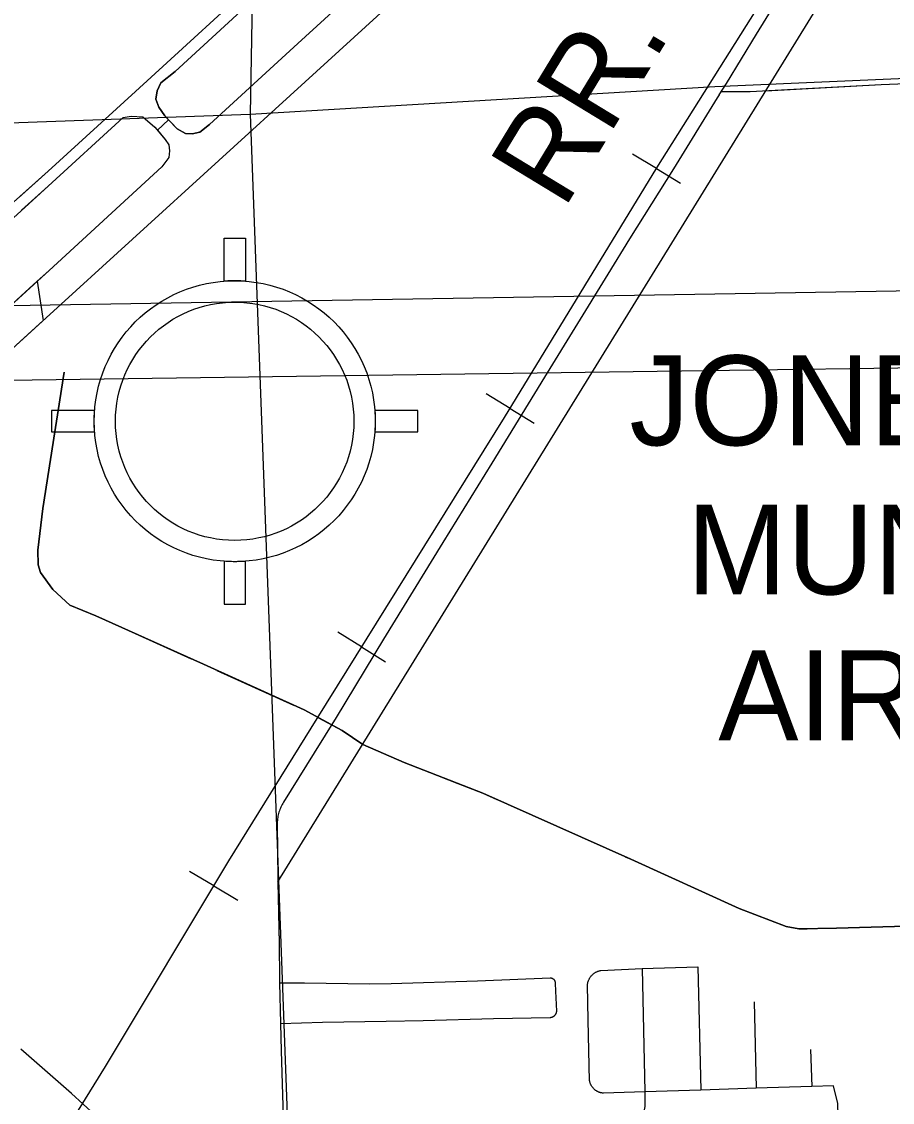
# Model space of a CAD drawing. Extents: x 646058 to 725608, y 1473014 to 1561048.
# Drawn here: x 652089 to 654134, y 1553140 to 1555679 of the extents above; entities that cross this region are included whole.
import ezdxf

# ---------------------------------------------------------------- set-up
doc = ezdxf.new("R2010")
doc.units = 0
doc.layers.add('Default', color=7, linetype='Continuous')

msp = doc.modelspace()

# ---------------------------------------------------------------- linework, layer by layer
at = {"layer": 'Default'}
for p, q in [((653579.7, 1555333.9), (653523.3, 1555368.3)), ((653579.7, 1555333.9), (653636, 1555299.6)), ((652564.4, 1555069.4), (652564.4, 1555170.4)), ((652564.4, 1555170.4), (652614.4, 1555170.4)), ((653236.1, 1554770.4), (653179.7, 1554804.8)), ((652260.3, 1554765.4), (652159.4, 1554765.4)), ((652159.4, 1554765.4), (652159.4, 1554715.4)), ((653019.4, 1554765.4), (652918.4, 1554765.4)), ((653019.4, 1554715.4), (653019.4, 1554765.4)), ((653236.1, 1554770.4), (653292.4, 1554736)), ((652614.4, 1554310.4), (652614.4, 1554411.3)), ((652564.4, 1554310.4), (652614.4, 1554310.4)), ((652887.3, 1554210.1), (652831.3, 1554245)), ((652887.3, 1554210.1), (652943.3, 1554175.2)), ((652540.1, 1553648.8), (652483.5, 1553682.7)), ((652540.1, 1553648.8), (652596.7, 1553614.9))]:
    msp.add_line(p, q, dxfattribs=at)
for points in [[(652603.7, 1558110.8), (652645.2, 1556568.6), (652625.6, 1555461.7)], [(652690.8, 1553657.9), (654107.8, 1555957.2), (654213.4, 1556124.9), (654316.1, 1556289.2), (654433.5, 1556478.3), (654545.6, 1556660.4), (654677, 1556873.8), (654783, 1557046.2), (654897.1, 1557233.3), (655061.6, 1557505.5), (655230.6, 1557774.9)], [(652151.1, 1555327.8), (652356.1, 1555515), (652677.9, 1555810.5), (653077.1, 1556176.4)], [(653077.1, 1556176.4), (652677.9, 1555810.5), (652356.1, 1555515), (652151.1, 1555327.8)], [(653097.4, 1556153.5), (652777.3, 1555864.2), (652449.3, 1555562.5), (652415.9, 1555535.2), (652407.1, 1555516.8), (652404.5, 1555497.4), (652411.5, 1555478.1), (652425.6, 1555457.8), (652454.6, 1555427.1), (652474, 1555416.5), (652489.8, 1555415.6), (652507.4, 1555420), (652530.2, 1555437.6), (652737.7, 1555627.6), (653219.6, 1556069.1)], [(652434.3, 1555448.6), (652425.6, 1555457.8), (652411.5, 1555478.1), (652404.5, 1555497.4), (652407.1, 1555516.8), (652415.9, 1555535.2), (652449.3, 1555562.5), (652777.3, 1555864.2), (653097.4, 1556153.5)], [(653219.6, 1556069.1), (652737.7, 1555627.6), (652530.2, 1555437.6), (652507.4, 1555420), (652489.8, 1555415.6), (652474, 1555416.5), (652454.6, 1555427.1), (652434.3, 1555448.6)], [(652146.4, 1554983.1), (652755.3, 1555537.5), (653286.4, 1556023.3)], [(652146.4, 1554983.1), (652755.3, 1555537.5), (653286.4, 1556023.3)], [(653727.1, 1555507.2), (653744.3, 1555534.3), (653815.2, 1555649.7), (653909.8, 1555804.3)], [(650469, 1550273.7), (650551.1, 1550406.6), (650698, 1550644.3), (650864.5, 1550916.9), (651062.8, 1551236.4), (651236.9, 1551521.1), (651402, 1551789.1), (651583.7, 1552081.4), (651698.7, 1552273.7), (651957.6, 1552696.2), (652122.6, 1552959.6), (652286.2, 1553224.6), (652575.3, 1553707.7), (652782.8, 1554042.3), (653223.3, 1554749.5), (653580.6, 1555335.5), (653813.8, 1555706.5)], [(650469, 1550273.7), (650551.1, 1550406.6), (650698, 1550644.3), (650864.5, 1550916.9), (651062.8, 1551236.4), (651236.9, 1551521.1), (651402, 1551789.1), (651583.7, 1552081.4), (651698.7, 1552273.7), (651957.6, 1552696.2), (652122.6, 1552959.6), (652286.2, 1553224.6), (652575.3, 1553707.7), (652782.8, 1554042.3), (653223.3, 1554749.5), (653580.6, 1555335.5), (653813.8, 1555706.5)], [(651957.6, 1552696.2), (652122.6, 1552959.6), (652286.2, 1553224.6), (652575.3, 1553707.7), (652782.8, 1554042.3), (653223.3, 1554749.5), (653580.6, 1555335.5), (653813.8, 1555706.5)], [(653732.3, 1555515.5), (653800.2, 1555515), (654107.4, 1555532), (654344.2, 1555541.3), (654528.4, 1555548.2), (654865, 1555563.7), (655077, 1555572.2), (655262.7, 1555580.8), (655436.8, 1555586.2), (655707.7, 1555594.7), (655830.7, 1555596.2), (655923.6, 1555600.1), (656045, 1555604), (656446.7, 1555620.2), (656625.4, 1555628), (656926.4, 1555639.6), (657231.3, 1555648.1), (657507.6, 1555658.2), (657676.3, 1555663.6), (657882.9, 1555670.5)], [(653836.5, 1555517), (654107.4, 1555532), (654344.2, 1555541.3), (654528.4, 1555548.2), (654865, 1555563.7), (655077, 1555572.2), (655262.7, 1555580.8), (655436.8, 1555586.2), (655707.7, 1555594.7), (655830.7, 1555596.2), (655923.6, 1555600.1), (656045, 1555604), (656446.7, 1555620.2), (656625.4, 1555628), (656926.4, 1555639.6), (657231.3, 1555648.1), (657507.6, 1555658.2), (657676.3, 1555663.6), (657882.9, 1555670.5)], [(652625.6, 1555461.7), (653716.8, 1555527), (655261.9, 1555594.5)], [(653727.1, 1555507.2), (653722.4, 1555499.9), (653619.7, 1555333.7), (653516.5, 1555169), (653465.4, 1555086.3), (653317.3, 1554844.1), (653193.1, 1554642.2), (653078.2, 1554455.3), (652938.8, 1554228.2), (652827.6, 1554044.2), (652775.8, 1553961.6), (652703.9, 1553845.4), (652702.3, 1553842.6), (652700.7, 1553839.8), (652699.3, 1553836.9), (652697.9, 1553834), (652696.6, 1553831), (652695.4, 1553828), (652694.4, 1553824.9), (652693.4, 1553821.8)], [(649972.5, 1555366.3), (652625.6, 1555461.7)], [(652151.1, 1555292.9), (652327.1, 1555453.9), (652346.5, 1555457.4), (652373.7, 1555455.7), (652401.9, 1555431), (652426.5, 1555402), (652434.4, 1555389.7), (652436.1, 1555375.6), (652434.4, 1555359.8), (652418.6, 1555337.8), (652153.4, 1555094.6)], [(652151.1, 1555292.9), (652327.1, 1555453.9), (652346.5, 1555457.4), (652373.7, 1555455.7), (652401.9, 1555431), (652407.9, 1555424)], [(652407.9, 1555424), (652434.3, 1555448.6)], [(652625.6, 1555461.7), (652721.9, 1552858.1)], [(652407.9, 1555424), (652426.5, 1555402), (652434.4, 1555389.7), (652436.1, 1555375.6), (652434.4, 1555359.8), (652418.6, 1555337.8), (652153.4, 1555094.6)], [(651734.2, 1555260.9), (651788.2, 1555306.1), (651799.1, 1555317), (651801.4, 1555332.5), (651800.6, 1555356.6), (651834, 1555357.4), (651837.9, 1555174.7), (651862.8, 1555161.5), (651864.3, 1555119.5), (651872.1, 1555105.5), (651879.9, 1555101.6), (651896.2, 1555102.4), (651906.3, 1555109.4), (652151.1, 1555327.8)], [(652151.1, 1555327.8), (652081.4, 1555265.6)], [(652151.1, 1555292.9), (651870.6, 1555036.4), (651874.4, 1554940), (651884.5, 1554920.5), (651900.9, 1554905.8), (651914.9, 1554901.1), (651934.3, 1554901.9), (651947.5, 1554908.1), (651963.8, 1554921.3), (652153.4, 1555094.6)], [(652089, 1555236.1), (652151.1, 1555292.9)], [(668379.5, 1555281.6), (649175.8, 1554963.8)], [(668379.5, 1555281.6), (649175.8, 1554963.8)], [(652614.4, 1555170.4), (652614.4, 1555069.4), (652611, 1555069.7), (652607.6, 1555069.9), (652604.2, 1555070.1), (652600, 1555070.2), (652596.3, 1555070.3), (652591.7, 1555070.4), (652588.8, 1555070.4), (652584.7, 1555070.4), (652580.8, 1555070.3), (652577.3, 1555070.2), (652573.3, 1555070), (652570.1, 1555069.8), (652567.2, 1555069.6), (652564.4, 1555069.4)], [(652153.4, 1555094.6), (652125.9, 1555069.5)], [(649175.8, 1554797.2), (668379.5, 1555063.1)], [(649175.8, 1554797.2), (668379.5, 1555063.1)], [(651874.4, 1554940), (651884.5, 1554920.5), (651900.9, 1554905.8), (651914.9, 1554901.1), (651934.3, 1554901.9), (651947.5, 1554908.1), (651963.8, 1554921.3), (652125.9, 1555069.5)], [(652125.9, 1555069.5), (652139.9, 1554977.2)], [(652125.9, 1555069.5), (652139.9, 1554977.2)], [(652146.4, 1554983.1), (651887.7, 1554747.6), (651885.3, 1554743.7), (651886.1, 1554708.8), (651895.4, 1554561.1), (651873.7, 1554539.3), (651872.9, 1554527.7), (651896.2, 1554061.3), (651909.1, 1553842.5)], [(652139.9, 1554977.2), (651887.7, 1554747.6), (651885.3, 1554743.7), (651886.1, 1554708.8), (651895.4, 1554561.1), (651873.7, 1554539.3), (651872.9, 1554527.7), (651895.7, 1554072)], [(654002.5, 1553549.5), (653914.5, 1553547.7), (653884.2, 1553553.2), (653774.2, 1553595.8), (653519.8, 1553711.3), (653171.9, 1553866.8), (652987.7, 1553938.3), (652890, 1553980.9), (652841.9, 1554013.9), (652752.5, 1554062.1), (652516, 1554169.4), (652263, 1554283.5), (652202.5, 1554308.3), (652162.6, 1554345.4), (652133.7, 1554385.3), (652128.2, 1554403.2), (652126.8, 1554437.6), (652139.2, 1554535.2), (652188.7, 1554855.7)], [(652188.7, 1554855.7), (652139.2, 1554535.2), (652126.8, 1554437.6), (652128.2, 1554403.2), (652133.7, 1554385.3), (652162.6, 1554345.4), (652202.5, 1554308.3), (652263, 1554283.5), (652516, 1554169.4), (652752.5, 1554062.1), (652841.9, 1554013.9), (652890, 1553980.9), (652987.7, 1553938.3), (653171.9, 1553866.8), (653519.8, 1553711.3), (653774.2, 1553595.8), (653884.2, 1553553.2), (653914.5, 1553547.7), (654002.5, 1553549.5)], [(652159.4, 1554715.4), (652260.3, 1554715.4), (652260.1, 1554718.2), (652259.9, 1554721.6), (652259.8, 1554724.4), (652259.7, 1554726.7), (652259.5, 1554729.8), (652259.5, 1554732.6), (652259.4, 1554736.8), (652259.4, 1554740.4), (652259.4, 1554744.3), (652259.5, 1554747.7), (652259.6, 1554751.1), (652259.6, 1554753.8), (652259.8, 1554756.9), (652259.9, 1554759.4), (652260.1, 1554761.5), (652260.2, 1554763.4), (652260.3, 1554765.4)], [(652918.4, 1554765.4), (652918.5, 1554764.2), (652918.6, 1554762.6), (652918.7, 1554761.3), (652918.8, 1554759.9), (652918.9, 1554758.2), (652919, 1554756.8), (652919, 1554755.1), (652919.1, 1554753.8), (652919.2, 1554751.9), (652919.2, 1554750.5), (652919.3, 1554749), (652919.3, 1554747.1), (652919.3, 1554745.5), (652919.4, 1554744), (652919.4, 1554742.2), (652919.4, 1554740.5), (652919.4, 1554738.6), (652919.4, 1554736.5), (652919.3, 1554734.6), (652919.3, 1554731.9), (652919.2, 1554729.3), (652919.1, 1554727.7), (652919, 1554725.5), (652918.9, 1554723.2), (652918.8, 1554720.3), (652918.6, 1554718.1), (652918.4, 1554715.4), (653019.4, 1554715.4)], [(652614.4, 1554411.3), (652612.7, 1554411.2), (652610.6, 1554411.1), (652607.9, 1554410.9), (652604.7, 1554410.8), (652601.9, 1554410.6), (652599.1, 1554410.5), (652596.1, 1554410.5), (652593.7, 1554410.4), (652590, 1554410.4), (652585.6, 1554410.4), (652582, 1554410.5), (652578.3, 1554410.6), (652575.3, 1554410.7), (652571.1, 1554410.9), (652568.4, 1554411.1), (652564.4, 1554411.3), (652564.4, 1554310.4)], [(652306.8, 1554263.7), (652487.3, 1554182.3)], [(652547.4, 1554155.1), (652727.7, 1554073.3)], [(652786.6, 1554043.7), (652841.9, 1554013.9), (652890, 1553980.9), (652960.5, 1553950.1)], [(653021.5, 1553925.1), (653113.8, 1553889.3)], [(653113.8, 1553889.3), (653171.9, 1553866.8), (653205.4, 1553851.8)], [(652693.4, 1553821.8), (652692.5, 1553818.7), (652691.8, 1553815.6), (652691.1, 1553812.4), (652690.5, 1553809.2), (652690.1, 1553806), (652689.7, 1553802.8), (652689.5, 1553799.5), (652689.4, 1553796.3), (652690.7, 1553664.2), (652693.9, 1553512.8), (652694.3, 1553431), (652694.6, 1553421.2)], [(653265.7, 1553824.9), (653446.5, 1553744.1)], [(653506.7, 1553717.2), (653519.8, 1553711.3), (653687, 1553635.4)], [(652690.8, 1553657.9), (652693.9, 1553512.8), (652694.3, 1553431), (652694.6, 1553421.2)], [(653747.1, 1553608.1), (653774.2, 1553595.8), (653884.2, 1553553.2), (653914.5, 1553547.7), (653934, 1553548.1)], [(656022.1, 1551653.3), (656016.5, 1551688.2), (656011.1, 1551986.3), (655995, 1552500.7), (655983, 1552926.4), (655973.6, 1553146.6), (655964.2, 1553556.2), (655958.8, 1553599.2), (655921.2, 1553607.3), (655746.6, 1553601.9), (655505, 1553596.5), (655347.9, 1553593.9), (655247.2, 1553587.1), (654926.3, 1553576.4), (654515.4, 1553565.6), (654193.2, 1553554.9), (654002.5, 1553549.5)], [(654002.5, 1553549.5), (654193.2, 1553554.9), (654515.4, 1553565.6), (654926.3, 1553576.4), (655247.2, 1553587.1), (655347.9, 1553593.9), (655505, 1553596.5), (655746.6, 1553601.9), (655921.2, 1553607.3), (655958.8, 1553599.2), (655964.2, 1553556.2), (655973.6, 1553146.6), (655976.4, 1553079.7)], [(654000, 1553549.5), (654002.5, 1553549.5)], [(654002.5, 1553549.5), (654101.5, 1553552.3)], [(653419.5, 1553333.2), (653417.7, 1553416.1), (653417.9, 1553417.5), (653418.2, 1553418.9), (653418.4, 1553420.2), (653418.7, 1553421.5), (653419.1, 1553422.9), (653419.5, 1553424.2), (653420, 1553425.5), (653420.5, 1553426.7), (653421, 1553428), (653421.6, 1553429.2), (653422.3, 1553430.4), (653422.9, 1553431.6), (653423.7, 1553432.8), (653424.4, 1553433.9), (653425.2, 1553435.1), (653426, 1553436.1), (653426.9, 1553437.2), (653427.8, 1553438.2)], [(653419.5, 1553333.2), (653417.7, 1553416.1), (653417.9, 1553417.5), (653418.2, 1553418.9), (653418.4, 1553420.2), (653418.7, 1553421.5), (653419.1, 1553422.9), (653419.5, 1553424.2), (653420, 1553425.5), (653420.5, 1553426.7), (653421, 1553428), (653421.6, 1553429.2), (653422.3, 1553430.4), (653422.9, 1553431.6), (653423.7, 1553432.8), (653424.4, 1553433.9), (653425.2, 1553435.1), (653426, 1553436.1), (653426.9, 1553437.2), (653427.8, 1553438.2)], [(653427.8, 1553438.2), (653428.8, 1553439.2), (653429.7, 1553440.2), (653430.8, 1553441.1), (653431.8, 1553442), (653432.9, 1553442.9), (653434, 1553443.7), (653435.1, 1553444.4), (653436.3, 1553445.2), (653437.4, 1553445.9), (653438.6, 1553446.5), (653439.9, 1553447.1), (653441.1, 1553447.7), (653442.4, 1553448.2), (653443.7, 1553448.7), (653445, 1553449.1), (653446.3, 1553449.5), (653447.6, 1553449.9), (653448.9, 1553450.2), (653546.3, 1553454.3)], [(653427.8, 1553438.2), (653428.8, 1553439.2), (653429.7, 1553440.2), (653430.8, 1553441.1), (653431.8, 1553442), (653432.9, 1553442.9), (653434, 1553443.7), (653435.1, 1553444.4), (653436.3, 1553445.2), (653437.4, 1553445.9), (653438.6, 1553446.5), (653439.9, 1553447.1), (653441.1, 1553447.7), (653442.4, 1553448.2), (653443.7, 1553448.7), (653445, 1553449.1), (653446.3, 1553449.5), (653447.6, 1553449.9), (653448.9, 1553450.2), (653546.3, 1553454.3)], [(653546.3, 1553454.3), (653676.8, 1553458.2)], [(653546.3, 1553454.3), (653676.8, 1553458.2)], [(653546.3, 1553454.3), (653552.8, 1553164.7)], [(653546.3, 1553454.3), (653552.8, 1553164.7)], [(653676.8, 1553458.2), (653684.2, 1553168.9)], [(653676.8, 1553458.2), (653684.2, 1553168.9)], [(652694.6, 1553421.2), (652753.4, 1553421.1), (652855.4, 1553419.4), (652906.1, 1553418.5), (652956.8, 1553419.3), (653160, 1553426), (653330.6, 1553432.8), (653331, 1553432.7), (653331.5, 1553432.7), (653331.9, 1553432.6), (653332.4, 1553432.5), (653332.8, 1553432.4), (653333.3, 1553432.3), (653333.7, 1553432.1), (653334.2, 1553432), (653334.6, 1553431.8), (653335, 1553431.6), (653335.4, 1553431.4), (653335.9, 1553431.2), (653336.3, 1553431), (653336.6, 1553430.7), (653337, 1553430.5), (653337.4, 1553430.2), (653337.8, 1553429.9), (653338.1, 1553429.7), (653338.5, 1553429.3), (653338.8, 1553429), (653339.2, 1553428.7)], [(652694.6, 1553421.2), (652753.4, 1553421.1), (652855.4, 1553419.4), (652906.1, 1553418.5), (652956.8, 1553419.3), (653160, 1553426), (653330.6, 1553432.8), (653331, 1553432.7), (653331.5, 1553432.7), (653331.9, 1553432.6), (653332.4, 1553432.5), (653332.8, 1553432.4), (653333.3, 1553432.3), (653333.7, 1553432.1), (653334.2, 1553432), (653334.6, 1553431.8), (653335, 1553431.6), (653335.4, 1553431.4), (653335.9, 1553431.2), (653336.3, 1553431), (653336.6, 1553430.7), (653337, 1553430.5), (653337.4, 1553430.2), (653337.8, 1553429.9), (653338.1, 1553429.7), (653338.5, 1553429.3), (653338.8, 1553429), (653339.2, 1553428.7)], [(652694.6, 1553421.2), (652697.1, 1553325.1)], [(652694.6, 1553421.2), (652697.1, 1553325.1)], [(653340.9, 1553344.1), (653341.3, 1553344.5), (653341.6, 1553344.9), (653342, 1553345.3), (653342.3, 1553345.7), (653342.6, 1553346.2), (653343, 1553346.6), (653343.3, 1553347), (653343.5, 1553347.5), (653343.8, 1553348), (653344.1, 1553348.4), (653344.3, 1553348.9), (653344.5, 1553349.4), (653344.7, 1553349.9), (653344.9, 1553350.4), (653345.1, 1553350.9), (653345.2, 1553351.4), (653345.3, 1553352), (653345.5, 1553352.5), (653345.6, 1553353), (653345.6, 1553353.5), (653345.7, 1553354.1), (653345.7, 1553354.6), (653343.9, 1553401), (653343, 1553420), (653342.9, 1553420.4), (653342.9, 1553420.9), (653342.8, 1553421.3), (653342.7, 1553421.8), (653342.6, 1553422.3), (653342.5, 1553422.7), (653342.4, 1553423.2), (653342.3, 1553423.6), (653342.1, 1553424), (653341.9, 1553424.5), (653341.8, 1553424.9), (653341.6, 1553425.3), (653341.3, 1553425.7), (653341.1, 1553426.1), (653340.9, 1553426.5), (653340.6, 1553426.9), (653340.4, 1553427.3), (653340.1, 1553427.7), (653339.8, 1553428), (653339.5, 1553428.4), (653339.2, 1553428.7)], [(653340.9, 1553344.1), (653341.3, 1553344.5), (653341.6, 1553344.9), (653342, 1553345.3), (653342.3, 1553345.7), (653342.6, 1553346.2), (653343, 1553346.6), (653343.3, 1553347), (653343.5, 1553347.5), (653343.8, 1553348), (653344.1, 1553348.4), (653344.3, 1553348.9), (653344.5, 1553349.4), (653344.7, 1553349.9), (653344.9, 1553350.4), (653345.1, 1553350.9), (653345.2, 1553351.4), (653345.3, 1553352), (653345.5, 1553352.5), (653345.6, 1553353), (653345.6, 1553353.5), (653345.7, 1553354.1), (653345.7, 1553354.6), (653343.9, 1553401), (653343, 1553420), (653342.9, 1553420.4), (653342.9, 1553420.9), (653342.8, 1553421.3), (653342.7, 1553421.8), (653342.6, 1553422.3), (653342.5, 1553422.7), (653342.4, 1553423.2), (653342.3, 1553423.6), (653342.1, 1553424), (653341.9, 1553424.5), (653341.8, 1553424.9), (653341.6, 1553425.3), (653341.3, 1553425.7), (653341.1, 1553426.1), (653340.9, 1553426.5), (653340.6, 1553426.9), (653340.4, 1553427.3), (653340.1, 1553427.7), (653339.8, 1553428), (653339.5, 1553428.4), (653339.2, 1553428.7)], [(653809.7, 1553375.9), (653813.9, 1553173.1)], [(653809.7, 1553375.9), (653813.9, 1553173.1)], [(652697.1, 1553325.1), (652795.3, 1553328.5), (652944.9, 1553330.7), (653032.4, 1553332.2), (653197.3, 1553336.8), (653330.2, 1553339.7), (653330.7, 1553339.7), (653331.3, 1553339.8), (653331.8, 1553339.8), (653332.3, 1553339.9), (653332.9, 1553340), (653333.4, 1553340.1), (653333.9, 1553340.2), (653334.4, 1553340.4), (653335, 1553340.6), (653335.5, 1553340.7), (653336, 1553340.9), (653336.4, 1553341.1), (653336.9, 1553341.4), (653337.4, 1553341.6), (653337.9, 1553341.9), (653338.3, 1553342.2), (653338.8, 1553342.5), (653339.2, 1553342.8), (653339.7, 1553343.1), (653340.1, 1553343.4), (653340.5, 1553343.8), (653340.9, 1553344.1)], [(652697.1, 1553325.1), (652795.3, 1553328.5), (652944.9, 1553330.7), (653032.4, 1553332.2), (653197.3, 1553336.8), (653330.2, 1553339.7), (653330.7, 1553339.7), (653331.3, 1553339.8), (653331.8, 1553339.8), (653332.3, 1553339.9), (653332.9, 1553340), (653333.4, 1553340.1), (653333.9, 1553340.2), (653334.4, 1553340.4), (653335, 1553340.6), (653335.5, 1553340.7), (653336, 1553340.9), (653336.4, 1553341.1), (653336.9, 1553341.4), (653337.4, 1553341.6), (653337.9, 1553341.9), (653338.3, 1553342.2), (653338.8, 1553342.5), (653339.2, 1553342.8), (653339.7, 1553343.1), (653340.1, 1553343.4), (653340.5, 1553343.8), (653340.9, 1553344.1)], [(652697.1, 1553325.1), (652698.8, 1553261.5), (652702.9, 1553105.9), (652703.1, 1553095.7)], [(652697.1, 1553325.1), (652698.8, 1553261.5), (652702.9, 1553105.9), (652703.1, 1553095.7)], [(653434.2, 1553170.5), (653433.3, 1553171.3), (653432.5, 1553172.2), (653431.7, 1553173), (653430.9, 1553173.9), (653430.2, 1553174.8), (653429.4, 1553175.7), (653428.8, 1553176.7), (653428.1, 1553177.7), (653427.5, 1553178.7), (653426.9, 1553179.7), (653426.4, 1553180.7), (653425.8, 1553181.8), (653425.4, 1553182.8), (653424.9, 1553183.9), (653424.5, 1553185), (653424.1, 1553186.1), (653423.8, 1553187.3), (653423.5, 1553188.4), (653423.3, 1553189.5), (653423, 1553190.7), (653419.5, 1553333.2)], [(653434.2, 1553170.5), (653433.3, 1553171.3), (653432.5, 1553172.2), (653431.7, 1553173), (653430.9, 1553173.9), (653430.2, 1553174.8), (653429.4, 1553175.7), (653428.8, 1553176.7), (653428.1, 1553177.7), (653427.5, 1553178.7), (653426.9, 1553179.7), (653426.4, 1553180.7), (653425.8, 1553181.8), (653425.4, 1553182.8), (653424.9, 1553183.9), (653424.5, 1553185), (653424.1, 1553186.1), (653423.8, 1553187.3), (653423.5, 1553188.4), (653423.3, 1553189.5), (653423, 1553190.7), (653419.5, 1553333.2)], [(652288.5, 1553085.7), (652206.3, 1553160.7), (652087.1, 1553265.3)], [(653941.8, 1553264.3), (653944.7, 1553177.3)], [(653941.8, 1553264.3), (653944.7, 1553177.3)], [(653552.8, 1553164.7), (653455.4, 1553161.7), (653454.2, 1553161.8), (653453.1, 1553161.9), (653451.9, 1553162.1), (653450.8, 1553162.3), (653449.6, 1553162.5), (653448.5, 1553162.8), (653447.4, 1553163.1), (653446.2, 1553163.5), (653445.1, 1553163.9), (653444, 1553164.3), (653443, 1553164.8), (653441.9, 1553165.3), (653440.9, 1553165.8), (653439.9, 1553166.4), (653438.9, 1553167), (653437.9, 1553167.7), (653436.9, 1553168.3), (653436, 1553169), (653435.1, 1553169.8), (653434.2, 1553170.5)], [(653552.8, 1553164.7), (653455.4, 1553161.7), (653454.2, 1553161.8), (653453.1, 1553161.9), (653451.9, 1553162.1), (653450.8, 1553162.3), (653449.6, 1553162.5), (653448.5, 1553162.8), (653447.4, 1553163.1), (653446.2, 1553163.5), (653445.1, 1553163.9), (653444, 1553164.3), (653443, 1553164.8), (653441.9, 1553165.3), (653440.9, 1553165.8), (653439.9, 1553166.4), (653438.9, 1553167), (653437.9, 1553167.7), (653436.9, 1553168.3), (653436, 1553169), (653435.1, 1553169.8), (653434.2, 1553170.5)], [(653552.8, 1553164.7), (653552.4, 1553130.5), (653551.4, 1553122.5), (653550.3, 1553114.6), (653548.9, 1553106.7), (653547.2, 1553098.8), (653545.7, 1553091.4), (653544.5, 1553084), (653543.5, 1553076.5), (653542.7, 1553069), (653542.2, 1553061.5), (653541.9, 1553053.9), (653541.9, 1553046.4), (653545, 1552863.1)], [(653552.8, 1553164.7), (653552.4, 1553130.5), (653551.4, 1553122.5), (653550.3, 1553114.6), (653548.9, 1553106.7), (653547.2, 1553098.8), (653545.7, 1553091.4), (653544.5, 1553084), (653543.5, 1553076.5), (653542.7, 1553069), (653542.2, 1553061.5), (653541.9, 1553053.9), (653541.9, 1553046.4), (653545, 1552863.1)], [(653684.2, 1553168.9), (653552.8, 1553164.7)], [(653684.2, 1553168.9), (653552.8, 1553164.7)], [(653813.9, 1553173.1), (653684.2, 1553168.9)], [(653813.9, 1553173.1), (653684.2, 1553168.9)], [(653944.7, 1553177.3), (653813.9, 1553173.1)], [(653944.7, 1553177.3), (653813.9, 1553173.1)], [(653995.8, 1553179), (653944.7, 1553177.3)], [(653995.8, 1553179), (653944.7, 1553177.3)], [(654014, 1552879.7), (654008.2, 1553050.9), (654006.2, 1553137.5), (653995.8, 1553179)], [(654014, 1552879.7), (654008.2, 1553050.9), (654006.2, 1553137.5), (653995.8, 1553179)]]:
    msp.add_lwpolyline(points, dxfattribs=at)
for radius in [330, 280]:
    msp.add_circle((652589.4, 1554740.4), radius, dxfattribs=at)

# ---------------------------------------------------------------- texts
msp.add_text('RR.', height=211.2, rotation=58.6877, dxfattribs=at).set_placement((653361.6, 1555234.8))
for s, p in [('JONESBORO', (653516.3, 1554683.9)), ('MUNICIPAL', (653651.3, 1554333.5)), ('AIRPORT', (653725.2, 1553990.7))]:
    msp.add_text(s, height=211.2, dxfattribs=at).set_placement(p)

doc.saveas('drawing.dxf')
